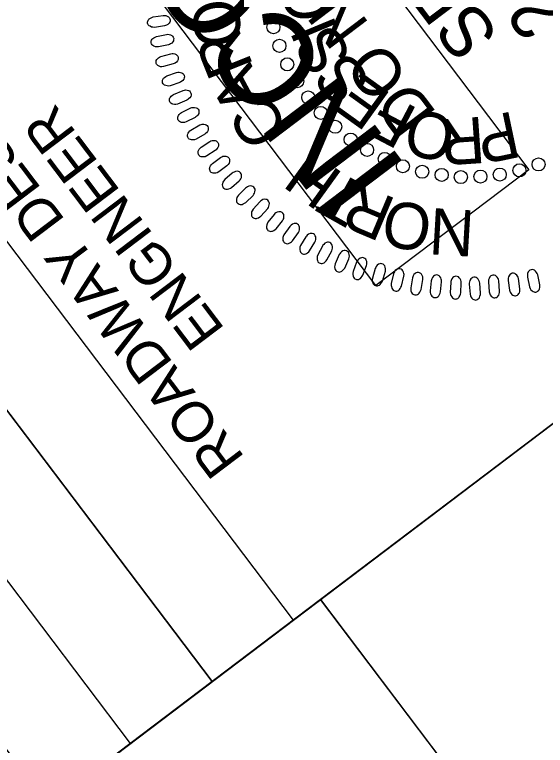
# Model space of a CAD drawing. Extents: x 475599 to 477488, y 499839 to 501843.
# Drawn here: x 475743.5 to 475808.5, y 501029.5 to 501118.9 of the extents above; entities that cross this region are included whole.
import ezdxf

# ---------------------------------------------------------------- set-up
doc = ezdxf.new("R2010")
doc.units = 0
for name, color, linetype in [('Prop Grid Mask', 7, 'Continuous'), ('Sheet Layout Plan Border', 7, 'Continuous'), ('Sheet PE Seal Cell', 7, 'Continuous'), ('Sheet Plan CELL', 7, 'Continuous'), ('Sheet Sticker Incomplete CELL', 7, 'Continuous')]:
    doc.layers.add(name, color=color, linetype=linetype)

msp = doc.modelspace()

# ---------------------------------------------------------------- linework, layer by layer
at = {"layer": 'Prop Grid Mask'}
msp.add_lwpolyline([(475747.692, 501022.154), (475842.669, 500896.68), (475875.923, 500921.851), (475780.946, 501047.326)], close=True, dxfattribs=at)
at = {"layer": 'Sheet Layout Plan Border'}
msp.add_lwpolyline([(477369.485, 500619.343), (476565.061, 501682.05), (476503.293, 501631.072), (476482.512, 501623.318), (476353.406, 501551.571), (476353.406, 501551.571), (475928.123, 501315.23), (475798.165, 501243.009), (475886.058, 501126.892), (475780.946, 501047.326), (475875.923, 500921.851), (475842.657, 500896.671), (476532.299, 499985.628)], close=True, dxfattribs=at)
at = {"layer": 'Sheet PE Seal Cell'}
for points in [[(475761.845, 501117.538), (475760.632, 501117.36), (475760.41, 501117.366), (475760.264, 501117.397), (475760.08, 501117.484), (475759.957, 501117.564), (475759.862, 501117.664), (475759.807, 501117.761), (475759.771, 501117.869), (475759.775, 501117.983), (475759.787, 501118.106), (475759.831, 501118.218), (475759.915, 501118.336), (475759.985, 501118.407), (475760.123, 501118.495), (475760.293, 501118.58), (475760.447, 501118.626), (475761.69, 501118.814), (475761.86, 501118.816), (475762.005, 501118.792), (475762.176, 501118.727), (475762.33, 501118.636), (475762.423, 501118.551), (475762.505, 501118.405), (475762.547, 501118.26), (475762.529, 501118.106), (475762.494, 501117.995), (475762.414, 501117.855), (475762.264, 501117.712), (475762.096, 501117.62), (475761.971, 501117.571)], [(475762.318, 501115.231), (475761.118, 501114.978), (475760.895, 501114.97), (475760.748, 501114.992), (475760.559, 501115.067), (475760.431, 501115.139), (475760.33, 501115.233), (475760.27, 501115.327), (475760.227, 501115.432), (475760.224, 501115.546), (475760.228, 501115.669), (475760.265, 501115.784), (475760.341, 501115.907), (475760.406, 501115.982), (475760.54, 501116.079), (475760.702, 501116.174), (475760.854, 501116.23), (475762.082, 501116.496), (475762.252, 501116.509), (475762.399, 501116.494), (475762.573, 501116.439), (475762.733, 501116.358), (475762.831, 501116.279), (475762.922, 501116.138), (475762.972, 501115.995), (475762.964, 501115.842), (475762.937, 501115.729), (475762.866, 501115.584), (475762.724, 501115.432), (475762.563, 501115.329), (475762.442, 501115.273)], [(475762.926, 501112.881), (475761.744, 501112.553), (475761.522, 501112.53), (475761.374, 501112.543), (475761.18, 501112.606), (475761.049, 501112.67), (475760.942, 501112.757), (475760.876, 501112.847), (475760.826, 501112.95), (475760.816, 501113.063), (475760.812, 501113.186), (475760.842, 501113.303), (475760.91, 501113.431), (475760.971, 501113.51), (475761.097, 501113.615), (475761.254, 501113.72), (475761.402, 501113.785), (475762.611, 501114.128), (475762.78, 501114.151), (475762.927, 501114.145), (475763.104, 501114.101), (475763.269, 501114.031), (475763.372, 501113.959), (475763.471, 501113.823), (475763.53, 501113.684), (475763.532, 501113.53), (475763.512, 501113.416), (475763.45, 501113.266), (475763.318, 501113.106), (475763.164, 501112.993), (475763.046, 501112.93)], [(475763.718, 501110.616), (475762.559, 501110.215), (475762.339, 501110.178), (475762.19, 501110.182), (475761.993, 501110.233), (475761.858, 501110.289), (475761.746, 501110.368), (475761.674, 501110.454), (475761.618, 501110.554), (475761.6, 501110.666), (475761.59, 501110.789), (475761.612, 501110.908), (475761.672, 501111.039), (475761.728, 501111.122), (475761.847, 501111.234), (475761.997, 501111.349), (475762.14, 501111.423), (475763.325, 501111.841), (475763.493, 501111.876), (475763.64, 501111.879), (475763.82, 501111.847), (475763.988, 501111.786), (475764.095, 501111.72), (475764.204, 501111.592), (475764.271, 501111.456), (475764.282, 501111.302), (475764.269, 501111.187), (475764.217, 501111.035), (475764.096, 501110.866), (475763.948, 501110.744), (475763.835, 501110.673)], [(475764.58, 501108.447), (475763.449, 501107.973), (475763.232, 501107.924), (475763.082, 501107.918), (475762.882, 501107.956), (475762.744, 501108.003), (475762.627, 501108.076), (475762.55, 501108.157), (475762.488, 501108.253), (475762.463, 501108.363), (475762.445, 501108.486), (475762.46, 501108.605), (475762.511, 501108.74), (475762.562, 501108.826), (475762.674, 501108.946), (475762.816, 501109.071), (475762.955, 501109.153), (475764.112, 501109.645), (475764.276, 501109.689), (475764.423, 501109.701), (475764.604, 501109.681), (475764.777, 501109.631), (475764.888, 501109.573), (475765.003, 501109.451), (475765.079, 501109.32), (475765.1, 501109.167), (475765.095, 501109.051), (475765.052, 501108.896), (475764.942, 501108.72), (475764.802, 501108.589), (475764.694, 501108.511)], [(475765.593, 501106.323), (475764.494, 501105.78), (475764.281, 501105.716), (475764.132, 501105.701), (475763.931, 501105.727), (475763.79, 501105.765), (475763.668, 501105.83), (475763.586, 501105.906), (475763.518, 501105.998), (475763.486, 501106.107), (475763.46, 501106.228), (475763.468, 501106.348), (475763.511, 501106.486), (475763.555, 501106.575), (475763.66, 501106.701), (475763.794, 501106.835), (475763.928, 501106.926), (475765.051, 501107.489), (475765.213, 501107.544), (475765.358, 501107.566), (475765.54, 501107.556), (475765.715, 501107.517), (475765.83, 501107.466), (475765.953, 501107.351), (475766.037, 501107.226), (475766.068, 501107.075), (475766.069, 501106.959), (475766.036, 501106.801), (475765.937, 501106.618), (475765.806, 501106.478), (475765.703, 501106.394)], [(475766.777, 501104.285), (475765.713, 501103.674), (475765.505, 501103.596), (475765.358, 501103.572), (475765.155, 501103.585), (475765.011, 501103.614), (475764.886, 501103.672), (475764.799, 501103.742), (475764.726, 501103.83), (475764.688, 501103.937), (475764.654, 501104.055), (475764.654, 501104.176), (475764.688, 501104.317), (475764.727, 501104.408), (475764.823, 501104.542), (475764.95, 501104.682), (475765.076, 501104.781), (475766.162, 501105.414), (475766.32, 501105.479), (475766.463, 501105.51), (475766.646, 501105.512), (475766.823, 501105.484), (475766.941, 501105.44), (475767.071, 501105.334), (475767.163, 501105.214), (475767.203, 501105.065), (475767.212, 501104.949), (475767.189, 501104.789), (475767.102, 501104.601), (475766.979, 501104.453), (475766.882, 501104.362)], [(475768.063, 501102.296), (475767.04, 501101.618), (475766.837, 501101.528), (475766.691, 501101.495), (475766.488, 501101.495), (475766.343, 501101.515), (475766.214, 501101.565), (475766.124, 501101.63), (475766.045, 501101.713), (475766, 501101.817), (475765.959, 501101.933), (475765.951, 501102.054), (475765.976, 501102.196), (475766.01, 501102.29), (475766.097, 501102.429), (475766.214, 501102.577), (475766.334, 501102.684), (475767.379, 501103.384), (475767.532, 501103.459), (475767.673, 501103.499), (475767.856, 501103.512), (475768.034, 501103.496), (475768.154, 501103.459), (475768.291, 501103.361), (475768.39, 501103.247), (475768.44, 501103.101), (475768.455, 501102.985), (475768.442, 501102.824), (475768.367, 501102.632), (475768.255, 501102.476), (475768.163, 501102.38)], [(475769.466, 501100.399), (475768.488, 501099.659), (475768.29, 501099.556), (475768.146, 501099.514), (475767.944, 501099.501), (475767.798, 501099.512), (475767.667, 501099.553), (475767.572, 501099.612), (475767.488, 501099.69), (475767.437, 501099.791), (475767.388, 501099.905), (475767.373, 501100.024), (475767.389, 501100.168), (475767.417, 501100.264), (475767.496, 501100.408), (475767.603, 501100.564), (475767.716, 501100.678), (475768.714, 501101.442), (475768.863, 501101.527), (475769.001, 501101.575), (475769.182, 501101.6), (475769.362, 501101.595), (475769.484, 501101.565), (475769.626, 501101.476), (475769.732, 501101.369), (475769.791, 501101.226), (475769.814, 501101.112), (475769.812, 501100.95), (475769.748, 501100.753), (475769.646, 501100.591), (475769.56, 501100.489)], [(475770.146, 501099.515), (475769.216, 501098.715), (475769.074, 501098.543), (475769.003, 501098.413), (475768.947, 501098.217), (475768.927, 501098.072), (475768.94, 501097.935), (475768.978, 501097.83), (475769.036, 501097.731), (475769.124, 501097.66), (475769.225, 501097.588), (475769.338, 501097.548), (475769.483, 501097.534), (475769.582, 501097.541), (475769.739, 501097.587), (475769.914, 501097.658), (475770.05, 501097.746), (475771.007, 501098.56), (475771.121, 501098.687), (475771.198, 501098.812), (475771.26, 501098.984), (475771.293, 501099.16), (475771.29, 501099.286), (475771.233, 501099.444), (475771.151, 501099.571), (475771.023, 501099.658), (475770.917, 501099.705), (475770.758, 501099.736), (475770.552, 501099.716), (475770.372, 501099.649), (475770.254, 501099.588)], [(475771.779, 501097.693), (475770.902, 501096.836), (475770.77, 501096.656), (475770.707, 501096.521), (475770.664, 501096.322), (475770.654, 501096.176), (475770.675, 501096.041), (475770.719, 501095.937), (475770.783, 501095.843), (475770.876, 501095.777), (475770.981, 501095.712), (475771.097, 501095.679), (475771.241, 501095.674), (475771.34, 501095.687), (475771.494, 501095.743), (475771.664, 501095.826), (475771.794, 501095.921), (475772.698, 501096.794), (475772.804, 501096.928), (475772.873, 501097.058), (475772.925, 501097.233), (475772.946, 501097.411), (475772.935, 501097.536), (475772.869, 501097.691), (475772.779, 501097.812), (475772.646, 501097.891), (475772.536, 501097.931), (475772.376, 501097.952), (475772.172, 501097.919), (475771.997, 501097.842), (475771.883, 501097.773)], [(475773.51, 501096.016), (475772.688, 501095.107), (475772.568, 501094.919), (475772.513, 501094.78), (475772.483, 501094.579), (475772.482, 501094.433), (475772.511, 501094.298), (475772.562, 501094.198), (475772.632, 501094.108), (475772.729, 501094.048), (475772.837, 501093.99), (475772.955, 501093.964), (475773.1, 501093.968), (475773.198, 501093.987), (475773.348, 501094.053), (475773.512, 501094.146), (475773.636, 501094.249), (475774.484, 501095.177), (475774.581, 501095.318), (475774.642, 501095.451), (475774.682, 501095.63), (475774.692, 501095.809), (475774.673, 501095.933), (475774.597, 501096.083), (475774.499, 501096.197), (475774.362, 501096.268), (475774.251, 501096.301), (475774.09, 501096.313), (475773.887, 501096.267), (475773.717, 501096.179), (475773.608, 501096.103)], [(475775.278, 501094.463), (475774.514, 501093.503), (475774.407, 501093.309), (475774.361, 501093.166), (475774.343, 501092.964), (475774.351, 501092.818), (475774.389, 501092.686), (475774.446, 501092.588), (475774.521, 501092.503), (475774.621, 501092.449), (475774.734, 501092.398), (475774.853, 501092.38), (475774.997, 501092.393), (475775.093, 501092.418), (475775.239, 501092.493), (475775.397, 501092.597), (475775.515, 501092.707), (475776.302, 501093.686), (475776.391, 501093.833), (475776.442, 501093.97), (475776.471, 501094.151), (475776.471, 501094.33), (475776.444, 501094.453), (475776.359, 501094.598), (475776.254, 501094.706), (475776.112, 501094.768), (475775.999, 501094.794), (475775.838, 501094.795), (475775.639, 501094.737), (475775.474, 501094.638), (475775.37, 501094.556)], [(475777.181, 501092.977), (475776.479, 501091.971), (475776.384, 501091.77), (475776.347, 501091.626), (475776.342, 501091.422), (475776.359, 501091.277), (475776.405, 501091.147), (475776.469, 501091.054), (475776.549, 501090.974), (475776.652, 501090.925), (475776.767, 501090.883), (475776.887, 501090.871), (475777.03, 501090.893), (475777.125, 501090.925), (475777.266, 501091.009), (475777.418, 501091.122), (475777.528, 501091.24), (475778.253, 501092.266), (475778.331, 501092.418), (475778.374, 501092.558), (475778.392, 501092.74), (475778.38, 501092.919), (475778.346, 501093.04), (475778.251, 501093.179), (475778.14, 501093.281), (475777.995, 501093.334), (475777.88, 501093.353), (475777.719, 501093.344), (475777.524, 501093.273), (475777.366, 501093.164), (475777.267, 501093.075)], [(475779.16, 501091.715), (475778.523, 501090.667), (475778.441, 501090.46), (475778.413, 501090.314), (475778.421, 501090.11), (475778.447, 501089.966), (475778.501, 501089.84), (475778.57, 501089.751), (475778.656, 501089.676), (475778.762, 501089.635), (475778.88, 501089.598), (475779, 501089.595), (475779.141, 501089.626), (475779.233, 501089.663), (475779.369, 501089.756), (475779.513, 501089.878), (475779.615, 501090.003), (475780.274, 501091.073), (475780.343, 501091.229), (475780.377, 501091.372), (475780.384, 501091.555), (475780.361, 501091.732), (475780.319, 501091.851), (475780.216, 501091.984), (475780.098, 501092.078), (475779.95, 501092.122), (475779.835, 501092.134), (475779.674, 501092.115), (475779.484, 501092.032), (475779.333, 501091.913), (475779.24, 501091.818)], [(475781.182, 501090.59), (475780.612, 501089.504), (475780.543, 501089.292), (475780.524, 501089.144), (475780.544, 501088.942), (475780.58, 501088.8), (475780.642, 501088.677), (475780.716, 501088.593), (475780.806, 501088.523), (475780.915, 501088.489), (475781.034, 501088.46), (475781.155, 501088.464), (475781.294, 501088.503), (475781.384, 501088.546), (475781.513, 501088.647), (475781.65, 501088.779), (475781.744, 501088.91), (475782.334, 501090.019), (475782.393, 501090.179), (475782.418, 501090.324), (475782.413, 501090.507), (475782.378, 501090.683), (475782.33, 501090.798), (475782.218, 501090.924), (475782.095, 501091.012), (475781.944, 501091.045), (475781.829, 501091.05), (475781.67, 501091.021), (475781.485, 501090.927), (475781.342, 501090.799), (475781.255, 501090.698)], [(475783.248, 501089.541), (475782.747, 501088.421), (475782.691, 501088.205), (475782.682, 501088.057), (475782.715, 501087.856), (475782.759, 501087.716), (475782.828, 501087.598), (475782.908, 501087.519), (475783.002, 501087.455), (475783.112, 501087.427), (475783.234, 501087.405), (475783.354, 501087.417), (475783.49, 501087.466), (475783.578, 501087.514), (475783.7, 501087.623), (475783.828, 501087.763), (475783.914, 501087.899), (475784.433, 501089.044), (475784.482, 501089.207), (475784.498, 501089.353), (475784.481, 501089.535), (475784.436, 501089.709), (475784.38, 501089.821), (475784.261, 501089.94), (475784.133, 501090.019), (475783.98, 501090.044), (475783.864, 501090.041), (475783.707, 501090.002), (475783.529, 501089.895), (475783.394, 501089.759), (475783.314, 501089.653)], [(475785.376, 501088.622), (475784.946, 501087.473), (475784.904, 501087.254), (475784.904, 501087.105), (475784.949, 501086.907), (475785.003, 501086.77), (475785.08, 501086.656), (475785.164, 501086.582), (475785.262, 501086.524), (475785.374, 501086.503), (475785.496, 501086.49), (475785.615, 501086.509), (475785.748, 501086.566), (475785.832, 501086.619), (475785.948, 501086.736), (475786.066, 501086.884), (475786.144, 501087.025), (475786.59, 501088.2), (475786.629, 501088.366), (475786.636, 501088.513), (475786.607, 501088.694), (475786.551, 501088.863), (475786.489, 501088.972), (475786.362, 501089.083), (475786.229, 501089.154), (475786.075, 501089.17), (475785.959, 501089.159), (475785.806, 501089.111), (475785.634, 501088.993), (475785.508, 501088.848), (475785.435, 501088.738)], [(475787.663, 501087.844), (475787.307, 501086.67), (475787.279, 501086.449), (475787.288, 501086.301), (475787.346, 501086.105), (475787.407, 501085.972), (475787.491, 501085.864), (475787.58, 501085.795), (475787.682, 501085.744), (475787.794, 501085.73), (475787.917, 501085.724), (475788.035, 501085.75), (475788.164, 501085.816), (475788.245, 501085.874), (475788.353, 501085.999), (475788.462, 501086.152), (475788.53, 501086.299), (475788.902, 501087.499), (475788.93, 501087.668), (475788.928, 501087.815), (475788.889, 501087.993), (475788.822, 501088.159), (475788.752, 501088.264), (475788.619, 501088.367), (475788.482, 501088.429), (475788.327, 501088.434), (475788.213, 501088.417), (475788.062, 501088.359), (475787.898, 501088.231), (475787.781, 501088.079), (475787.715, 501087.963)], [(475789.906, 501087.183), (475789.624, 501085.989), (475789.61, 501085.767), (475789.628, 501085.619), (475789.698, 501085.429), (475789.767, 501085.299), (475789.858, 501085.196), (475789.951, 501085.133), (475790.056, 501085.088), (475790.17, 501085.081), (475790.293, 501085.083), (475790.409, 501085.117), (475790.533, 501085.19), (475790.61, 501085.254), (475790.71, 501085.385), (475790.81, 501085.545), (475790.868, 501085.696), (475791.164, 501086.916), (475791.181, 501087.087), (475791.169, 501087.233), (475791.119, 501087.408), (475791.042, 501087.57), (475790.966, 501087.671), (475790.827, 501087.765), (475790.686, 501087.818), (475790.531, 501087.813), (475790.418, 501087.79), (475790.271, 501087.722), (475790.116, 501087.584), (475790.01, 501087.425), (475789.95, 501087.305)], [(475792.212, 501086.687), (475792.005, 501085.477), (475792.005, 501085.255), (475792.033, 501085.108), (475792.115, 501084.922), (475792.192, 501084.798), (475792.289, 501084.7), (475792.386, 501084.643), (475792.493, 501084.604), (475792.607, 501084.605), (475792.73, 501084.615), (475792.843, 501084.656), (475792.963, 501084.737), (475793.036, 501084.805), (475793.127, 501084.941), (475793.216, 501085.108), (475793.265, 501085.261), (475793.484, 501086.499), (475793.491, 501086.67), (475793.47, 501086.815), (475793.408, 501086.987), (475793.321, 501087.145), (475793.239, 501087.24), (475793.094, 501087.325), (475792.95, 501087.369), (475792.796, 501087.355), (475792.684, 501087.324), (475792.542, 501087.247), (475792.396, 501087.101), (475792.3, 501086.934), (475792.248, 501086.812)], [(475803.94, 501086.386), (475804.118, 501085.172), (475804.186, 501084.961), (475804.258, 501084.83), (475804.394, 501084.678), (475804.506, 501084.584), (475804.628, 501084.521), (475804.737, 501084.497), (475804.851, 501084.493), (475804.959, 501084.529), (475805.073, 501084.576), (475805.168, 501084.65), (475805.257, 501084.764), (475805.305, 501084.851), (475805.35, 501085.009), (475805.383, 501085.196), (475805.382, 501085.357), (475805.208, 501086.601), (475805.162, 501086.766), (475805.097, 501086.897), (475804.985, 501087.042), (475804.854, 501087.165), (475804.746, 501087.229), (475804.582, 501087.266), (475804.431, 501087.263), (475804.29, 501087.203), (475804.193, 501087.139), (475804.081, 501087.021), (475803.988, 501086.837), (475803.947, 501086.649), (475803.936, 501086.516)], [(475806.303, 501086.784), (475806.556, 501085.584), (475806.638, 501085.376), (475806.718, 501085.25), (475806.862, 501085.108), (475806.98, 501085.02), (475807.106, 501084.966), (475807.217, 501084.948), (475807.331, 501084.952), (475807.436, 501084.994), (475807.547, 501085.049), (475807.637, 501085.128), (475807.719, 501085.248), (475807.761, 501085.338), (475807.796, 501085.498), (475807.818, 501085.687), (475807.807, 501085.847), (475807.555, 501087.079), (475807.498, 501087.239), (475807.425, 501087.367), (475807.304, 501087.504), (475807.166, 501087.618), (475807.055, 501087.676), (475806.888, 501087.703), (475806.738, 501087.691), (475806.6, 501087.621), (475806.508, 501087.55), (475806.404, 501087.427), (475806.322, 501087.236), (475806.293, 501087.047), (475806.291, 501086.913)], [(475794.498, 501086.332), (475794.368, 501085.113), (475794.382, 501084.89), (475794.419, 501084.746), (475794.513, 501084.565), (475794.597, 501084.446), (475794.7, 501084.355), (475794.8, 501084.304), (475794.91, 501084.272), (475795.023, 501084.28), (475795.145, 501084.298), (475795.255, 501084.345), (475795.37, 501084.433), (475795.438, 501084.507), (475795.522, 501084.648), (475795.6, 501084.82), (475795.64, 501084.977), (475795.78, 501086.225), (475795.775, 501086.396), (475795.746, 501086.54), (475795.673, 501086.708), (475795.577, 501086.859), (475795.489, 501086.949), (475795.339, 501087.025), (475795.192, 501087.06), (475795.04, 501087.036), (475794.93, 501086.998), (475794.793, 501086.912), (475794.656, 501086.756), (475794.57, 501086.585), (475794.527, 501086.46)], [(475796.897, 501086.124), (475796.843, 501084.899), (475796.871, 501084.678), (475796.917, 501084.536), (475797.022, 501084.362), (475797.114, 501084.248), (475797.222, 501084.164), (475797.325, 501084.12), (475797.437, 501084.095), (475797.55, 501084.109), (475797.67, 501084.135), (475797.777, 501084.189), (475797.886, 501084.284), (475797.95, 501084.361), (475798.023, 501084.508), (475798.091, 501084.685), (475798.12, 501084.843), (475798.182, 501086.098), (475798.168, 501086.269), (475798.129, 501086.41), (475798.046, 501086.574), (475797.94, 501086.717), (475797.846, 501086.801), (475797.692, 501086.868), (475797.544, 501086.895), (475797.393, 501086.861), (475797.286, 501086.816), (475797.154, 501086.722), (475797.028, 501086.558), (475796.953, 501086.382), (475796.917, 501086.253)], [(475799.174, 501085.936), (475799.265, 501084.713), (475799.319, 501084.497), (475799.381, 501084.361), (475799.505, 501084.2), (475799.61, 501084.098), (475799.728, 501084.028), (475799.835, 501083.996), (475799.949, 501083.984), (475800.059, 501084.012), (475800.176, 501084.051), (475800.276, 501084.118), (475800.373, 501084.225), (475800.427, 501084.309), (475800.483, 501084.463), (475800.529, 501084.647), (475800.54, 501084.808), (475800.454, 501086.061), (475800.419, 501086.229), (475800.364, 501086.365), (475800.262, 501086.517), (475800.141, 501086.648), (475800.037, 501086.72), (475799.876, 501086.768), (475799.726, 501086.777), (475799.58, 501086.726), (475799.479, 501086.669), (475799.36, 501086.56), (475799.253, 501086.382), (475799.199, 501086.198), (475799.179, 501086.066)], [(475801.52, 501086.189), (475801.62, 501084.966), (475801.676, 501084.751), (475801.739, 501084.616), (475801.865, 501084.455), (475801.971, 501084.354), (475802.089, 501084.284), (475802.196, 501084.253), (475802.31, 501084.242), (475802.42, 501084.272), (475802.537, 501084.311), (475802.636, 501084.379), (475802.732, 501084.487), (475802.786, 501084.572), (475802.84, 501084.727), (475802.885, 501084.91), (475802.894, 501085.071), (475802.798, 501086.324), (475802.762, 501086.491), (475802.706, 501086.627), (475802.604, 501086.778), (475802.481, 501086.908), (475802.377, 501086.98), (475802.216, 501087.026), (475802.065, 501087.034), (475801.92, 501086.982), (475801.819, 501086.924), (475801.7, 501086.814), (475801.596, 501086.636), (475801.543, 501086.451), (475801.524, 501086.319)]]:
    msp.add_lwpolyline(points, close=True, dxfattribs=at)
for centre in [(475775.185, 501117.385), (475775.919, 501115.095), (475776.884, 501112.829), (475778.102, 501110.756), (475779.448, 501108.779), (475780.977, 501106.89), (475782.76, 501105.193), (475784.646, 501103.624), (475786.658, 501102.351), (475788.816, 501101.257), (475791.05, 501100.351), (475805.311, 501099.856), (475807.658, 501100.583), (475793.402, 501099.685), (475795.794, 501099.297), (475798.144, 501099.028), (475800.542, 501099.095), (475802.907, 501099.336)]:
    msp.add_circle(centre, 0.801, dxfattribs=at)
at = {"layer": 'Sheet Plan CELL'}
for p, q in [((475767.682, 501037.272), (475646.932, 501196.754)), ((475767.682, 501037.272), (475646.932, 501196.754)), ((475757.693, 501029.695), (475636.965, 501189.21)), ((475767.682, 501037.272), (475777.638, 501044.809))]:
    msp.add_line(p, q, dxfattribs=at)
for points in [[(477369.494, 500619.368), (476532.299, 499985.628), (475747.678, 501022.142), (475867.321, 501112.709), (475746.601, 501272.214), (476464.153, 501815.359)], [(475747.679, 501022.131), (475626.936, 501181.665), (475646.932, 501196.754), (475767.682, 501037.272)], [(475777.638, 501044.809), (475717.254, 501124.582), (475806.965, 501192.488), (475867.321, 501112.709)]]:
    msp.add_lwpolyline(points, close=True, dxfattribs=at)
at = {"layer": 'Sheet Sticker Incomplete CELL'}
msp.add_lwpolyline([(475806.465, 501099.927), (475787.727, 501085.744), (475699.007, 501202.952), (475717.745, 501217.135)], close=True, dxfattribs=at)

# ---------------------------------------------------------------- texts
at = {"layer": 'Sheet PE Seal Cell'}
for s, height, rotation, p in [('29470', 6.2363, 127.105, (475811.214, 501118.929)), ('SEAL', 6.2363, 127.105, (475802.979, 501116.422)), ('O', 5.669, 96.65348, (475782.388, 501118.455)), ('O', 5.669, 98.75389, (475771.502, 501115.374)), ('I', 5.669, 112.53307, (475783.158, 501117.152)), ('R', 5.669, 111.7326, (475772.764, 501112.623)), ('S', 5.669, 120.47287, (475784.948, 501113.741)), ('A', 5.669, 118.22196, (475774.67, 501108.79)), ('S', 5.669, 128.41267, (475787.359, 501110.724)), ('E', 5.669, 144.29226, (475789.794, 501109.096)), ('C', 5.669, 124.71131, (475777.265, 501105.016)), ('F', 5.669, 152.23206, (475793.067, 501107.322)), ('O', 5.669, 168.11166, (475797.801, 501106.268)), ('P', 5.669, 191.93105, (475804.564, 501107.123)), ('R', 5.669, 183.99125, (475800.866, 501106.438)), ('H', 5.669, 144.17938, (475783.9, 501099.372)), ('T', 5.669, 150.66874, (475786.943, 501097.688)), ('R', 5.669, 157.1581, (475790.417, 501096.278)), ('O', 5.669, 170.13681, (475794.929, 501095.334)), ('N', 5.669, 176.62617, (475799.943, 501094.932))]:
    msp.add_text(s, height=height, rotation=rotation, dxfattribs=at).set_placement(p)
at = {"layer": 'Sheet Plan CELL'}
for s, p in [('ROADWAY DESIGN', (475771.765, 501064.663)), ('ENGINEER', (475769.333, 501080.365))]:
    msp.add_text(s, height=5.0001, rotation=127.12364, dxfattribs=at).set_placement(p)
at = {"layer": 'Sheet Sticker Incomplete CELL'}
for s, height, p in [('INCOMPLETE PLANS', 11.52, (475791.734, 501100.002)), ('DO NOT USE FOR R/W ACQUISITION', 5.76, (475795.314, 501106.788))]:
    msp.add_text(s, height=height, rotation=127.12364, dxfattribs=at).set_placement(p)

doc.saveas('drawing.dxf')
